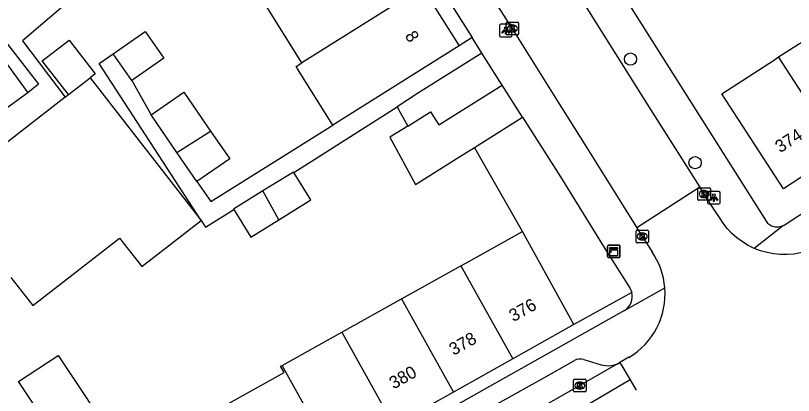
# Model space of a CAD drawing. Extents: x 159222 to 160346, y 381249 to 382166.
# Drawn here: x 159936.5 to 159998.6, y 381517.5 to 381547.9 of the extents above; entities that cross this region are included whole.
import ezdxf

# ---------------------------------------------------------------- set-up
doc = ezdxf.new("R2010")
doc.units = 0
for name, color, linetype in [('IMGEO_Boom', 7, 'Continuous'), ('IMGEO_Kast', 7, 'Continuous'), ('IMGEO_Kolk', 7, 'Continuous'), ('IMGEO_Lichtpunt', 7, 'Continuous'), ('IMGEO_Muur', 7, 'Continuous'), ('IMGEO_Pand', 7, 'Continuous'), ('IMGEO_Pand_nummerreeks', 7, 'Continuous'), ('IMGEO_Parkeervlak_open', 7, 'Continuous'), ('IMGEO_Rijbaan_lokaal_gesloten', 7, 'Continuous'), ('IMGEO_Rijbaan_lokaal_open', 7, 'Continuous'), ('IMGEO_Voetpad_open', 7, 'Continuous')]:
    doc.layers.add(name, color=color, linetype=linetype)

msp = doc.modelspace()

# ---------------------------------------------------------------- linework, layer by layer
at = {"layer": 'IMGEO_Boom'}
for centre in [(159985.611, 381544.37), (159990.766, 381536.082)]:
    msp.add_circle(centre, 0.489, dxfattribs=at)
at = {"layer": 'IMGEO_Kast'}
for p, q in [((159983.767, 381528.572), (159983.767, 381529.413)), ((159983.767, 381529.413), (159983.767, 381528.572)), ((159983.842, 381529.497), (159984.683, 381529.497)), ((159984.683, 381529.497), (159983.842, 381529.497)), ((159984.767, 381529.422), (159984.767, 381528.581)), ((159984.767, 381528.581), (159984.767, 381529.422)), ((159984.692, 381528.497), (159983.851, 381528.497)), ((159983.851, 381528.497), (159984.692, 381528.497))]:
    msp.add_line(p, q, dxfattribs=at)
for points in [[(159983.962, 381529.287), (159984.562, 381529.287), (159984.562, 381529.202), (159983.962, 381529.202), (159983.962, 381529.287)], [(159983.962, 381529.112), (159984.562, 381529.112), (159984.562, 381528.623), (159983.962, 381528.623), (159983.962, 381529.112)]]:
    msp.add_lwpolyline(points, dxfattribs=at)
msp.add_circle((159984.046, 381528.961), 0.0377, dxfattribs=at)
for centre, start, end in [((159983.845, 381529.419), 92.4484, 184.28452), ((159983.845, 381529.419), 92.4484, 184.28452), ((159984.689, 381529.419), 2.4484, 94.28452), ((159984.689, 381529.419), 2.4484, 94.28452), ((159983.845, 381528.575), 182.4484, 274.28452), ((159983.845, 381528.575), 182.4484, 274.28452), ((159984.689, 381528.575), 272.4484, 4.28452), ((159984.689, 381528.575), 272.4484, 4.28452)]:
    msp.add_arc(centre, 0.0779, start, end, dxfattribs=at)
at = {"layer": 'IMGEO_Kolk'}
for p, q in [((159975.665, 381546.398), (159975.665, 381547.25)), ((159975.74, 381547.324), (159976.592, 381547.324)), ((159976.153, 381547.104), (159976.178, 381547.104)), ((159976.666, 381547.25), (159976.666, 381546.398)), ((159976.176, 381546.544), (159976.151, 381546.544)), ((159976.592, 381546.324), (159975.74, 381546.324)), ((159991.002, 381533.149), (159991.002, 381534.001)), ((159991.077, 381534.075), (159991.929, 381534.075)), ((159992.003, 381534.001), (159992.003, 381533.149)), ((159991.49, 381533.855), (159991.515, 381533.855)), ((159991.929, 381533.075), (159991.077, 381533.075)), ((159991.513, 381533.295), (159991.488, 381533.295)), ((159986.05, 381529.757), (159986.05, 381530.609)), ((159986.125, 381530.683), (159986.977, 381530.683)), ((159986.538, 381530.463), (159986.563, 381530.463)), ((159987.051, 381530.609), (159987.051, 381529.757)), ((159986.977, 381529.683), (159986.125, 381529.683)), ((159986.561, 381529.903), (159986.536, 381529.903)), ((159981.062, 381517.827), (159981.062, 381518.679)), ((159981.137, 381518.753), (159981.989, 381518.753)), ((159981.55, 381518.533), (159981.575, 381518.533)), ((159982.063, 381518.679), (159982.063, 381517.827)), ((159981.573, 381517.973), (159981.548, 381517.973)), ((159981.989, 381517.753), (159981.137, 381517.753))]:
    msp.add_line(p, q, dxfattribs=at)
for points in [[(159975.665, 381546.398), (159975.665, 381547.25)], [(159975.74, 381547.324), (159976.592, 381547.324)], [(159975.986, 381547.024), (159976.109, 381547.024), (159976.109, 381546.873), (159976.239, 381547.024), (159976.403, 381547.024), (159976.257, 381546.873), (159976.41, 381546.624), (159976.258, 381546.624), (159976.173, 381546.788), (159976.109, 381546.721), (159976.109, 381546.624), (159975.986, 381546.624), (159975.986, 381547.024)], [(159976.666, 381547.25), (159976.666, 381546.398)], [(159976.592, 381546.324), (159975.74, 381546.324)], [(159991.002, 381533.149), (159991.002, 381534.001)], [(159991.077, 381534.075), (159991.929, 381534.075)], [(159992.003, 381534.001), (159992.003, 381533.149)], [(159991.323, 381533.775), (159991.446, 381533.775), (159991.446, 381533.624), (159991.576, 381533.775), (159991.74, 381533.775), (159991.594, 381533.624), (159991.747, 381533.375), (159991.595, 381533.375), (159991.51, 381533.539), (159991.446, 381533.472), (159991.446, 381533.375), (159991.323, 381533.375), (159991.323, 381533.775)], [(159991.929, 381533.075), (159991.077, 381533.075)], [(159986.05, 381529.757), (159986.05, 381530.609)], [(159986.125, 381530.683), (159986.977, 381530.683)], [(159986.371, 381530.383), (159986.494, 381530.383), (159986.494, 381530.232), (159986.624, 381530.383), (159986.788, 381530.383), (159986.642, 381530.232), (159986.795, 381529.983), (159986.643, 381529.983), (159986.558, 381530.147), (159986.494, 381530.08), (159986.494, 381529.983), (159986.371, 381529.983), (159986.371, 381530.383)], [(159987.051, 381530.609), (159987.051, 381529.757)], [(159986.977, 381529.683), (159986.125, 381529.683)], [(159981.062, 381517.827), (159981.062, 381518.679)], [(159981.137, 381518.753), (159981.989, 381518.753)], [(159981.383, 381518.453), (159981.506, 381518.453), (159981.506, 381518.302), (159981.636, 381518.453), (159981.8, 381518.453), (159981.654, 381518.302), (159981.807, 381518.053), (159981.655, 381518.053), (159981.57, 381518.217), (159981.506, 381518.15), (159981.506, 381518.053), (159981.383, 381518.053), (159981.383, 381518.453)], [(159982.063, 381518.679), (159982.063, 381517.827)], [(159981.989, 381517.753), (159981.137, 381517.753)]]:
    msp.add_lwpolyline(points, dxfattribs=at)
for centre, start, end in [((159975.742, 381547.248), 91.55205, 178.44795), ((159975.742, 381547.248), 91.55205, 178.44795), ((159976.59, 381547.248), 1.55205, 88.44795), ((159976.59, 381547.248), 1.55205, 88.44795), ((159975.742, 381546.4), 181.55205, 268.44795), ((159975.742, 381546.4), 181.55205, 268.44795), ((159976.59, 381546.4), 271.55205, 358.44795), ((159976.59, 381546.4), 271.55205, 358.44795), ((159991.079, 381533.999), 91.55205, 178.44795), ((159991.079, 381533.999), 91.55205, 178.44795), ((159991.927, 381533.999), 1.55205, 88.44795), ((159991.927, 381533.999), 1.55205, 88.44795), ((159991.079, 381533.151), 181.55205, 268.44795), ((159991.079, 381533.151), 181.55205, 268.44795), ((159991.927, 381533.151), 271.55205, 358.44795), ((159991.927, 381533.151), 271.55205, 358.44795), ((159986.127, 381530.607), 91.55205, 178.44795), ((159986.127, 381530.607), 91.55205, 178.44795), ((159986.975, 381530.607), 1.55205, 88.44795), ((159986.975, 381530.607), 1.55205, 88.44795), ((159986.127, 381529.759), 181.55205, 268.44795), ((159986.127, 381529.759), 181.55205, 268.44795), ((159986.975, 381529.759), 271.55205, 358.44795), ((159986.975, 381529.759), 271.55205, 358.44795), ((159981.139, 381518.677), 91.55205, 178.44795), ((159981.139, 381518.677), 91.55205, 178.44795), ((159981.987, 381518.677), 1.55205, 88.44795), ((159981.987, 381518.677), 1.55205, 88.44795), ((159981.139, 381517.829), 181.55205, 268.44795), ((159981.139, 381517.829), 181.55205, 268.44795), ((159981.987, 381517.829), 271.55205, 358.44795), ((159981.987, 381517.829), 271.55205, 358.44795)]:
    msp.add_arc(centre, 0.0765, start, end, dxfattribs=at)
for centre, major_axis, ratio, start_param, end_param in [((159976.152, 381546.824), (-0.387, 0.002), 0.722429, 4.712389, 7.853982), ((159976.177, 381546.824), (-0.39, 0.002), 0.717154, 1.570796, 4.712389), ((159991.489, 381533.575), (-0.387, 0.002), 0.722429, 4.712389, 7.853982), ((159991.514, 381533.575), (-0.39, 0.002), 0.717154, 1.570796, 4.712389), ((159986.537, 381530.183), (-0.387, 0.002), 0.722429, 4.712389, 7.853982), ((159986.562, 381530.183), (-0.39, 0.002), 0.717154, 1.570796, 4.712389), ((159981.549, 381518.253), (-0.387, 0.002), 0.722429, 4.712389, 7.853982), ((159981.574, 381518.253), (-0.39, 0.002), 0.717154, 1.570796, 4.712389)]:
    msp.add_ellipse(centre, major_axis=major_axis, ratio=ratio, start_param=start_param, end_param=end_param, dxfattribs=at)
at = {"layer": 'IMGEO_Lichtpunt'}
for p, q in [((159975.137, 381547.058), (159975.137, 381546.251)), ((159975.137, 381547.058), (159975.137, 381546.251)), ((159976.039, 381547.153), (159975.231, 381547.153)), ((159976.039, 381547.153), (159975.231, 381547.153)), ((159976.133, 381546.251), (159976.133, 381547.058)), ((159976.133, 381546.251), (159976.133, 381547.058)), ((159975.231, 381546.157), (159976.039, 381546.157)), ((159975.231, 381546.157), (159976.039, 381546.157)), ((159991.771, 381533.683), (159991.771, 381532.876)), ((159991.771, 381533.683), (159991.771, 381532.876)), ((159992.673, 381533.778), (159991.865, 381533.778)), ((159992.673, 381533.778), (159991.865, 381533.778)), ((159992.767, 381532.876), (159992.767, 381533.683)), ((159992.767, 381532.876), (159992.767, 381533.683)), ((159991.865, 381532.782), (159992.673, 381532.782)), ((159991.865, 381532.782), (159992.673, 381532.782))]:
    msp.add_line(p, q, dxfattribs=at)
for points in [[(159975.511, 381546.722), (159975.55, 381546.694), (159975.362, 381546.432), (159975.324, 381546.459), (159975.511, 381546.722)], [(159975.613, 381546.674), (159975.66, 381546.674), (159975.66, 381546.352), (159975.613, 381546.352), (159975.613, 381546.674)], [(159975.723, 381546.694), (159975.761, 381546.721), (159975.948, 381546.459), (159975.909, 381546.431), (159975.723, 381546.694)], [(159992.145, 381533.347), (159992.184, 381533.319), (159991.996, 381533.057), (159991.958, 381533.084), (159992.145, 381533.347)], [(159992.357, 381533.319), (159992.395, 381533.346), (159992.582, 381533.084), (159992.543, 381533.056), (159992.357, 381533.319)], [(159992.247, 381533.299), (159992.294, 381533.299), (159992.294, 381532.977), (159992.247, 381532.977), (159992.247, 381533.299)]]:
    msp.add_lwpolyline(points, dxfattribs=at)
for centre in [(159975.636, 381546.856), (159992.27, 381533.481)]:
    msp.add_circle(centre, 0.0994, dxfattribs=at)
for centre, start, end in [((159975.231, 381547.058), 90, 180), ((159975.231, 381547.058), 90, 180), ((159976.039, 381547.058), 0, 90), ((159976.039, 381547.058), 0, 90), ((159975.231, 381546.251), 180, 270), ((159975.231, 381546.251), 180, 270), ((159976.039, 381546.251), 270, 0), ((159976.039, 381546.251), 270, 360), ((159991.865, 381533.683), 90, 180), ((159991.865, 381533.683), 90, 180), ((159992.673, 381533.683), 0, 90), ((159992.673, 381533.683), 0, 90), ((159991.865, 381532.876), 180, 270), ((159991.865, 381532.876), 180, 270), ((159992.673, 381532.876), 270, 0), ((159992.673, 381532.876), 270, 360)]:
    msp.add_arc(centre, 0.0946, start, end, dxfattribs=at)
at = {"layer": 'IMGEO_Muur'}
msp.add_lwpolyline([(159976.979, 381530.577), (159973.133, 381537.305)], dxfattribs=at)
at = {"layer": 'IMGEO_Pand'}
for points in [[(159968.969, 381550.128), (159959.345, 381544.079)], [(159968.969, 381550.128), (159971.915, 381545.442)], [(159959.345, 381544.079), (159956.478, 381548.641)], [(159997.445, 381544.54), (160000, 381546.19), (160001.975, 381547.465)], [(159944.255, 381544.797), (159946.817, 381546.584), (159948.314, 381544.437), (159945.752, 381542.65)], [(159940.685, 381541.532), (159938.589, 381544.23), (159940.733, 381545.896), (159942.829, 381543.198), (159942.422, 381542.882)], [(159971.915, 381545.442), (159961.824, 381539.096)], [(159930.383, 381541.263), (159935.183, 381544.762), (159937.43, 381541.679)], [(159945.752, 381542.65), (159944.255, 381544.797)], [(159973.736, 381544.855), (159968.666, 381541.668), (159966.963, 381540.552)], [(159975.35, 381542.289), (159973.736, 381544.855)], [(160002.372, 381536.934), (160000, 381535.401), (159997.834, 381534.001), (159992.91, 381541.604), (159997.107, 381544.322), (159997.445, 381544.54)], [(160002.372, 381536.934), (160000, 381540.596), (159997.445, 381544.54)], [(159961.824, 381539.096), (159958.996, 381543.594), (159958.876, 381543.784), (159959.345, 381544.079)], [(159940.685, 381541.532), (159942.422, 381542.882)], [(159942.422, 381542.882), (159951.3, 381531.456)], [(159967.803, 381539.015), (159969.617, 381540.156), (159970.281, 381539.099), (159975.35, 381542.289)], [(159976.968, 381539.715), (159975.35, 381542.289)], [(159937.43, 381541.679), (159932.655, 381538.198)], [(159940.421, 381541.327), (159940.685, 381541.532)], [(159947.286, 381539.908), (159949.901, 381541.712), (159952.05, 381538.597)], [(159940.421, 381541.327), (159930.743, 381533.808)], [(159966.963, 381540.552), (159967.181, 381540.153), (159967.546, 381539.486), (159967.803, 381539.015)], [(159949.36, 381536.9), (159947.286, 381539.908)], [(159973.133, 381537.305), (159976.968, 381539.715)], [(159967.803, 381539.015), (159966.371, 381538.114), (159968.43, 381534.346), (159971.898, 381536.528), (159973.133, 381537.305)], [(159949.36, 381536.9), (159952.05, 381538.597)], [(159952.05, 381538.597), (159953.571, 381536.391), (159950.955, 381534.587)], [(159950.955, 381534.587), (159949.36, 381536.9)], [(159958.702, 381535.298), (159958.678, 381535.337), (159956.231, 381533.821)], [(159957.509, 381531.524), (159960.06, 381533.105), (159958.702, 381535.298)], [(159956.231, 381533.821), (159953.885, 381532.367), (159953.909, 381532.329)], [(159957.509, 381531.524), (159956.231, 381533.821)], [(159953.909, 381532.329), (159955.267, 381530.135), (159957.509, 381531.524)], [(159936.091, 381526.907), (159937.833, 381524.664), (159944.772, 381530.056), (159946.55, 381527.767), (159951.3, 381531.456)], [(159972.057, 381527.828), (159972.434, 381528.038), (159976.979, 381530.577)], [(159981.084, 381523.146), (159976.979, 381530.577)], [(159967.315, 381525.187), (159972.057, 381527.828)], [(159972.057, 381527.828), (159976.195, 381520.396)], [(159962.523, 381522.519), (159967.315, 381525.187)], [(159967.315, 381525.187), (159971.465, 381517.735)], [(159981.084, 381523.146), (159976.195, 381520.396)], [(159957.756, 381519.864), (159962.523, 381522.519)], [(159962.523, 381522.519), (159966.684, 381515.046)], [(159938.451, 381511.392), (159940.662, 381512.606), (159936.701, 381518.567), (159939.862, 381520.667), (159944.587, 381513.556), (159946.533, 381511.32), (159947.215, 381510.079), (159949.693, 381505.566)], [(159976.195, 381520.396), (159971.465, 381517.735)], [(159953.236, 381507.481), (159950.803, 381511.85), (159949.328, 381514.498), (159957.929, 381519.288), (159957.643, 381519.801), (159957.756, 381519.864)], [(159961.928, 381512.37), (159957.756, 381519.864)], [(159971.465, 381517.735), (159966.684, 381515.046)]]:
    msp.add_lwpolyline(points, dxfattribs=at)
at = {"layer": 'IMGEO_Parkeervlak_open'}
for points in [[(159976.979, 381530.577), (159973.133, 381537.305)], [(159985.706, 381525.704), (159981.084, 381523.146)]]:
    msp.add_lwpolyline(points, dxfattribs=at)
at = {"layer": 'IMGEO_Rijbaan_lokaal_gesloten'}
for points in [[(159991.154, 381534.117), (159986.125, 381530.86)], [(159995.5, 381529.226), (159995.015, 381529.463), (159994.553, 381529.742), (159994.118, 381530.062), (159993.713, 381530.419), (159993.342, 381530.812), (159993.008, 381531.235), (159992.712, 381531.687), (159992.362, 381532.212), (159991.498, 381533.574), (159991.154, 381534.117)], [(159986.125, 381530.86), (159986.549, 381530.183), (159987.328, 381528.952)], [(160001.488, 381529.889), (160001.002, 381529.578), (160000, 381529.099), (159999.723, 381529.004), (159999.201, 381528.865), (159998.669, 381528.773), (159998.131, 381528.729), (159997.592, 381528.733), (159997.054, 381528.785), (159996.524, 381528.886), (159996.004, 381529.033), (159995.5, 381529.226)], [(159985.484, 381520.511), (159984.765, 381520.088)], [(159984.765, 381520.088), (159981.56, 381518.252), (159979.447, 381517.045), (159975.155, 381514.62), (159971.047, 381512.378), (159967.809, 381510.629), (159964.388, 381508.825), (159958.736, 381505.908), (159955.499, 381504.24)], [(159984.765, 381520.088), (159985.577, 381518.699)], [(159985.577, 381518.699), (159980.645, 381515.791), (159956.076, 381502.58), (159939.951, 381494.362), (159923.443, 381485.375), (159911.619, 381478.616), (159897.952, 381470.628), (159877.989, 381459.107), (159830.923, 381432.992), (159823.666, 381428.97)], [(159985.577, 381518.699), (159986.055, 381517.88), (159986.055, 381517.88)]]:
    msp.add_lwpolyline(points, dxfattribs=at)
for centre, radius, start, end in [((159982.453, 381525.599), 5.917, 4.56597, 34.51987), ((159982.451, 381525.594), 5.92, 300.82647, 4.60958)]:
    msp.add_arc(centre, radius, start, end, dxfattribs=at)
at = {"layer": 'IMGEO_Rijbaan_lokaal_open'}
for points in [[(159939.094, 381623.231), (159950.113, 381605.587), (159954.758, 381598.275), (159957.08, 381592.897), (159960.157, 381585.77), (159960.913, 381584.02), (159962.843, 381579.548), (159970.562, 381566.909), (159981.67, 381549.205), (159987.216, 381540.342), (159991.154, 381534.117)], [(159953.876, 381583.269), (159954.185, 381582.593), (159954.441, 381581.964), (159954.682, 381581.33), (159956.627, 381577.595), (159959.688, 381572.722), (159965.798, 381562.997), (159976.297, 381546.548), (159979.506, 381541.419), (159982.163, 381537.186), (159983.357, 381535.276), (159985.364, 381532.074), (159986.125, 381530.86)]]:
    msp.add_lwpolyline(points, dxfattribs=at)
at = {"layer": 'IMGEO_Voetpad_open'}
for points in [[(159997.825, 381531.064), (159997.877, 381531.093), (160000, 381532.468), (160024.711, 381548.473), (160061.199, 381571.915)], [(159961.234, 381564.542), (159972.947, 381546.097)], [(159948.011, 381555.101), (159944.404, 381552.153), (159937.02, 381545.819), (159940.421, 381541.327)], [(159981.154, 381555.607), (159996.445, 381531.405), (159996.504, 381531.328), (159996.57, 381531.257), (159996.642, 381531.192), (159996.719, 381531.134), (159996.802, 381531.083), (159996.888, 381531.04), (159996.978, 381531.004), (159997.071, 381530.977), (159997.166, 381530.958), (159997.262, 381530.947), (159997.359, 381530.946), (159997.456, 381530.952), (159997.551, 381530.968), (159997.645, 381530.992), (159997.736, 381531.024), (159997.825, 381531.064)], [(159939.706, 381551.301), (159939.717, 381551.28), (159937.546, 381549.84), (159934.06, 381547.814), (159938.301, 381542.356), (159937.43, 381541.679)], [(159972.947, 381546.097), (159971.915, 381545.442)], [(159973.736, 381544.855), (159972.947, 381546.097)], [(159951.3, 381531.456), (159943.138, 381544.018), (159944.255, 381544.797)], [(159945.752, 381542.65), (159947.286, 381539.908)], [(159958.702, 381535.298), (159966.963, 381540.552)], [(159976.968, 381539.715), (159980.016, 381534.943), (159983.501, 381529.306), (159985.588, 381526.009), (159985.706, 381525.704)], [(159950.955, 381534.587), (159952.061, 381532.983), (159961.824, 381539.096)], [(159951.3, 381531.456), (159951.644, 381530.926), (159953.909, 381532.329)], [(159997.825, 381531.064), (159995.5, 381529.226)], [(159985.135, 381524.27), (159988.351, 381526.07)], [(159985.135, 381524.27), (159962.511, 381511.514), (159961.928, 381512.37)], [(159981.873, 381520.348), (159983.266, 381519.922)], [(159966.183, 381512.003), (159972.374, 381515.356), (159978.49, 381518.775), (159981.125, 381520.259)]]:
    msp.add_lwpolyline(points, dxfattribs=at)
for centre, radius, start, end in [((159984.475, 381525.364), 1.277, 301.11636, 15.46004), ((159981.624, 381519.252), 1.124, 77.20406, 116.3667), ((159983.822, 381521.751), 1.912, 253.09008, 299.54835)]:
    msp.add_arc(centre, radius, start, end, dxfattribs=at)

# ---------------------------------------------------------------- texts
at = {"layer": 'IMGEO_Pand_nummerreeks'}
for s, rotation, p in [('8', 302.15826, (159967.54, 381546.239)), ('374', 32.88012, (159997.577, 381536.835)), ('376', 29.35854, (159976.253, 381523.32)), ('378', 29.35854, (159971.467, 381520.627)), ('380', 29.35854, (159966.678, 381517.933))]:
    msp.add_text(s, height=1, rotation=rotation, dxfattribs=at).set_placement(p)

doc.saveas('drawing.dxf')
